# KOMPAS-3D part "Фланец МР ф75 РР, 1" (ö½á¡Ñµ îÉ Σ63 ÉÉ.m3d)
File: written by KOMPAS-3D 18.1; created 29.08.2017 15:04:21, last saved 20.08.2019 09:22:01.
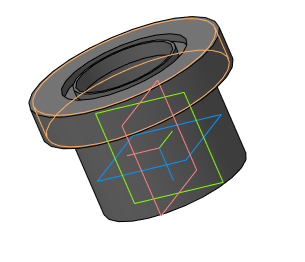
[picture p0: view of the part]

Document properties: Автор: Милов; Организация: Милов; Полное имя файла: D:\1 ПКИ 3D\Полипропиленовые фитинги, трубы\Разборные муфты\Фланец МР ф63 РР.m3d

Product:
- Part/product: Фланец МР ф75 РР  | designation 1
    Материал: Полипропилен  ГОСТ 26996-86 (density 900 kg/m3)
    Масса: 0.139269
  - Body: Тело 1
      Материал: Полипропилен  ГОСТ 26996-86 (density 0.9 kg/m3)
- Part/product: Фланец МР ф63 РР  | designation 01
    Материал: Полипропилен  ГОСТ 26996-86 (density 900 kg/m3)
    Масса: 0.139269
  - Body: Тело 1
      Материал: Полипропилен  ГОСТ 26996-86 (density 0.9 kg/m3)
- Part/product: Фланец МР ф63 РР
    Материал: Полипропилен  ГОСТ 26996-86 (density 900 kg/m3)
    Масса: 0.139269
  - Body: Тело 1
      Материал: Полипропилен  ГОСТ 26996-86 (density 0.9 kg/m3)

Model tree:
1. Эскиз:1
2. Операция вращения:1
     Угол 1 = 360
3. Условное изображение резьбы:1  (labels: Tr 100 ·4)
     Длина резьбы = 17.5; Шаг резьбы = 4; Номинальный диаметр резьбы = 100
4. Подгонка:1
5. Эскиз:2
6. Вырезать элемент выдавливания:1
     Расстояние 1 = 4.2
7. Операция выдавливания:1
     Расстояние 1 = 20
8. Операция выдавливания:2  (labels: Полипропилен  ГОСТ 26996-86)
     Расстояние 1 = 61
9. Масштабирование:1  (labels: Полипропилен  ГОСТ 26996-86; 3258069702-394-0-0|0)
     Коэффициент = 1.21359

Expressions: 75/2; 61.8/2; 51/2; cil4_24737-81
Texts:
  Body Specification ( left align )
  Body Specificaton ( centered )

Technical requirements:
  Gost Type A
